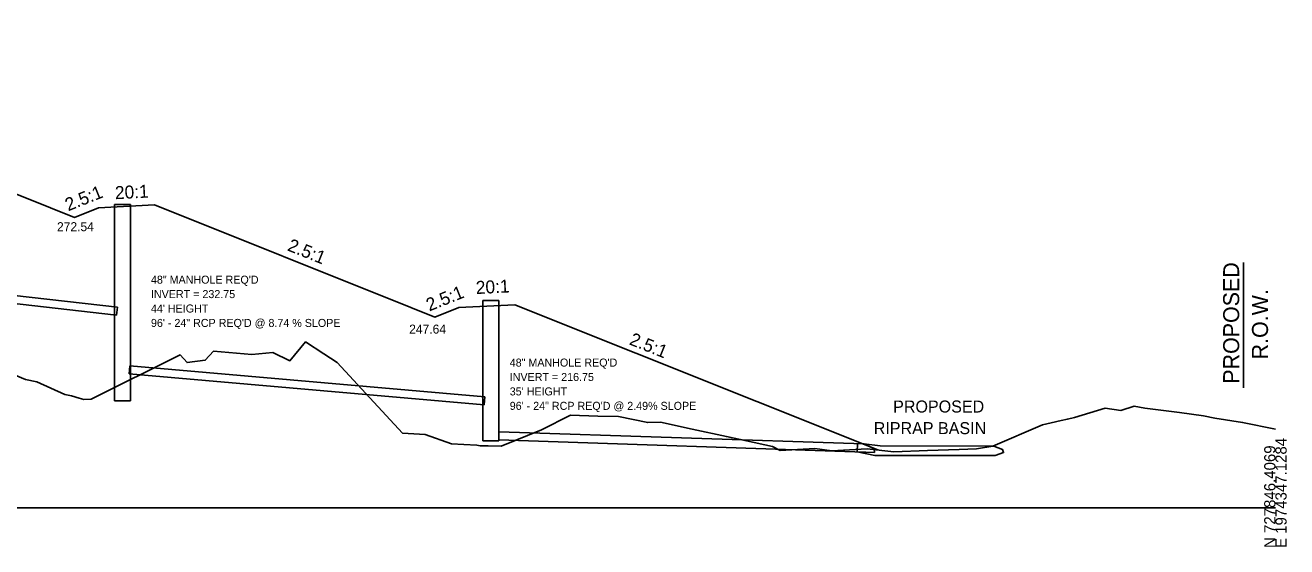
# Model space of a CAD drawing. Extents: x -26 to 1604, y -13 to 9623.
# Drawn here: x 287.7 to 602.8, y 6490.3 to 6620.5 of the extents above; entities that cross this region are included whole.
import ezdxf

# ---------------------------------------------------------------- set-up
doc = ezdxf.new("R2010")
doc.units = 0
for name, color, linetype in [('1', 7, 'Continuous'), ('DTM_X_GROUND', 7, 'Continuous'), ('SLOPE_STAKES_FILL', 7, 'Continuous'), ('XS_CELL', 7, 'Continuous'), ('XS_P_DRAINAGE', 7, 'Continuous'), ('XS_P_GROUND', 7, 'Continuous'), ('XS_P_ROW', 7, 'Continuous'), ('XS_P_TX_DCH', 7, 'Continuous'), ('XS_P_TX_FS_BS', 7, 'Continuous')]:
    doc.layers.add(name, color=color, linetype=linetype)

msp = doc.modelspace()

# ---------------------------------------------------------------- linework, layer by layer
at = {"layer": '1'}
msp.add_lwpolyline([(495.49, 6513.97), (499.96, 6513.11), (529.96, 6513.11), (532.09, 6513.8), (531.84, 6514.58), (529.62, 6515.44), (501.29, 6515.53), (497.14, 6515.99), (499.87, 6514.78), (499.81, 6513.85)], close=True, dxfattribs=at)
at = {"layer": 'DTM_X_GROUND'}
msp.add_lwpolyline([(279.32, 6535.56), (287.76, 6532.1), (290.59, 6531.51), (297.61, 6528.29), (299.25, 6527.95), (301.12, 6527.41), (302.34, 6527.06), (304.19, 6527.17), (326.41, 6538.22), (328.1, 6536.3), (332.66, 6536.89), (334.75, 6539.17), (344.26, 6538.28), (349.56, 6538.84), (353.79, 6536.74), (357.7, 6541.46), (362.3, 6538.45), (365.63, 6536.28), (381.97, 6518.67), (387.59, 6518.32), (394.13, 6516.01), (397.29, 6515.83), (400.54, 6515.64), (401.31, 6515.52), (403.3, 6515.48), (406.6, 6515.39), (416.62, 6519.52), (423.88, 6523.12), (430.75, 6522.95), (435.88, 6522.82), (443.21, 6521.31), (446.36, 6521.41), (454.3, 6519.68), (462.87, 6517.82), (467.84, 6516.77), (474.37, 6515.34), (476.32, 6514.32), (484.98, 6514.87), (489.19, 6514.29), (498.05, 6514.74), (504.71, 6514), (513.09, 6514.32), (521, 6514.61), (525.35, 6514.78), (529.44, 6515.42), (541.8, 6520.72), (544, 6521.24), (546.45, 6521.81), (548.02, 6522.18), (549.81, 6522.6), (557.43, 6524.9), (561.42, 6524.29), (564.68, 6525.43), (567.39, 6524.93), (576.08, 6523.84), (582.01, 6523), (584.84, 6522.42), (591.82, 6521.33), (600, 6519.68)], dxfattribs=at)
at = {"layer": 'XS_CELL'}
msp.add_line((100, 6500), (600, 6500), dxfattribs=at)
at = {"layer": 'XS_P_DRAINAGE'}
for p, q in [((310, 6526.75), (310, 6575.75)), ((310, 6575.75), (314, 6575.75)), ((314, 6526.75), (314, 6575.75)), ((226.59, 6559.69), (310.7, 6550.14)), ((226.36, 6557.7), (310.47, 6548.15)), ((310.47, 6548.15), (310.7, 6550.14)), ((402, 6516.75), (402, 6551.75)), ((402, 6551.75), (406, 6551.75)), ((406, 6516.75), (406, 6551.75)), ((313.65, 6533.51), (313.82, 6535.51)), ((313.65, 6533.51), (402.35, 6525.76)), ((313.82, 6535.51), (402.52, 6527.75)), ((402.52, 6527.75), (402.35, 6525.76)), ((310, 6526.75), (314, 6526.75)), ((497.14, 6515.99), (406.06, 6519)), ((402, 6516.75), (406, 6516.75)), ((499.81, 6513.85), (406, 6517)), ((495.61, 6516.03), (495.49, 6513.97)), ((497.14, 6515.99), (499.87, 6514.78)), ((499.87, 6514.78), (499.81, 6513.84))]:
    msp.add_line(p, q, dxfattribs=at)
at = {"layer": 'XS_P_GROUND'}
msp.add_lwpolyline([(142, 6620.51), (204, 6599.84), (210, 6597.84), (216, 6599.84), (230, 6600.54), (294, 6574.94), (300, 6572.54), (306, 6574.94), (320, 6575.64), (384, 6550.04), (390, 6547.64), (396, 6550.04), (410, 6550.74), (500.66, 6514.48)], dxfattribs=at)
at = {"layer": 'XS_P_ROW'}
msp.add_line((592, 6561.27), (592, 6530), dxfattribs=at)

# ---------------------------------------------------------------- texts
at = {"layer": '1'}
for s, p in [('PROPOSED', (504.51, 6523.82)), ('RIPRAP BASIN', (499.66, 6518.42))]:
    msp.add_text(s, height=3, dxfattribs=at).set_placement(p)
at = {"layer": 'SLOPE_STAKES_FILL'}
for p in [(293.96, 6574.88), (305.96, 6574.88), (319.96, 6575.58), (299.96, 6572.48), (383.96, 6549.98), (395.96, 6549.98), (409.96, 6550.68), (389.96, 6547.58)]:
    msp.add_text('X', height=0.12, dxfattribs=at).set_placement(p)
at = {"layer": 'XS_CELL'}
for s, p in [('N 727846.4069', (600, 6490)), ('E 1974347.1284', (602.8, 6490))]:
    msp.add_text(s, height=2.8, rotation=90, dxfattribs=at).set_placement(p)
at = {"layer": 'XS_P_DRAINAGE'}
for s, p in [('48" MANHOLE REQ\'D', (319.09, 6555.99)), ('INVERT = 232.75', (319.09, 6552.39)), ("44' HEIGHT", (319.09, 6548.79)), ('96\' - 24" RCP REQ\'D @ 8.74 % SLOPE', (319.09, 6545.19)), ('48" MANHOLE REQ\'D', (408.72, 6535.29)), ('INVERT = 216.75', (408.72, 6531.69)), ("35' HEIGHT", (408.72, 6528.09)), ('96\' - 24" RCP REQ\'D @ 2.49% SLOPE', (408.72, 6524.49))]:
    msp.add_text(s, height=2, dxfattribs=at).set_placement(p)
at = {"layer": 'XS_P_GROUND'}
msp.add_text('X', height=0.12, dxfattribs=at).set_placement((497.12, 6514.42))
at = {"layer": 'XS_P_ROW'}
for s, p in [('PROPOSED', (590.95, 6531.02)), ('R.O.W.', (598.15, 6537.09))]:
    msp.add_text(s, height=4, rotation=90, dxfattribs=at).set_placement(p)
at = {"layer": 'XS_P_TX_DCH'}
for s, p in [('272.54', (295.62, 6569.09)), ('247.64', (383.6, 6543.52))]:
    msp.add_text(s, height=2.25, dxfattribs=at).set_placement(p)
at = {"layer": 'XS_P_TX_FS_BS'}
for s, rotation, p in [('20:1', 2.8624, (310.17, 6577.07)), ('2.5:1', 21.8014, (298.42, 6574.04)), ('2.5:1', 338.1986, (352.97, 6564.34)), ('20:1', 2.8624, (400.32, 6553.39)), ('2.5:1', 21.8014, (388.63, 6549.03)), ('2.5:1', 338.1986, (438.37, 6540.88))]:
    msp.add_text(s, height=3.24, rotation=rotation, dxfattribs=at).set_placement(p)

doc.saveas('drawing.dxf')
